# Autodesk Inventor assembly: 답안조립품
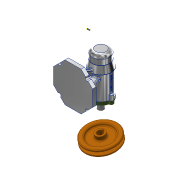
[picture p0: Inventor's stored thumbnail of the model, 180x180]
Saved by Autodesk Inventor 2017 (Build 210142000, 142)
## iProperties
Created: 2019-12
Part Number: 답안조립품
Document SubType Name: Assembly
Designer: 5-06-le-1
Author: 5-06-le-1
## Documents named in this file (12)
- C:\Users\5-06-le-1\Desktop\491204V1007\답안조립품.iam
- C:\Users\5-06-le-1\Desktop\491204V1007\본체.ipt
- C:\Users\5-06-le-1\Desktop\491204V1007\V벨트풀리.ipt
- C:\Users\5-06-le-1\Desktop\491204V1007\멈춤나사 M3.ipt
- C:\Users\5-06-le-1\Desktop\491204V1007\베어링 6004.ipt
- C:\Users\5-06-le-1\Desktop\491204V1007\베어링 51202.ipt
- C:\Users\5-06-le-1\Desktop\491204V1007\볼트 M4.ipt
- C:\Users\5-06-le-1\Desktop\491204V1007\어댑터슬리브.ipt
- C:\Users\5-06-le-1\Desktop\491204V1007\오일 실.ipt
- C:\Users\5-06-le-1\Desktop\491204V1007\축.ipt
- C:\Users\5-06-le-1\Desktop\491204V1007\커버.ipt
- C:\Users\5-06-le-1\Desktop\491204V1007\키 5 x 5 x 16.ipt
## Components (1 placed, 1 different names)
1. V벨트풀리:1
